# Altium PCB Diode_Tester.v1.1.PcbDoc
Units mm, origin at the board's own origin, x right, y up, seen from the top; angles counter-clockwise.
Board outline 69.07 x 78.33 mm, 2 copper layers (Top Layer, Bottom Layer); 64 components, 44 nets, 206 pads, 103 vias.
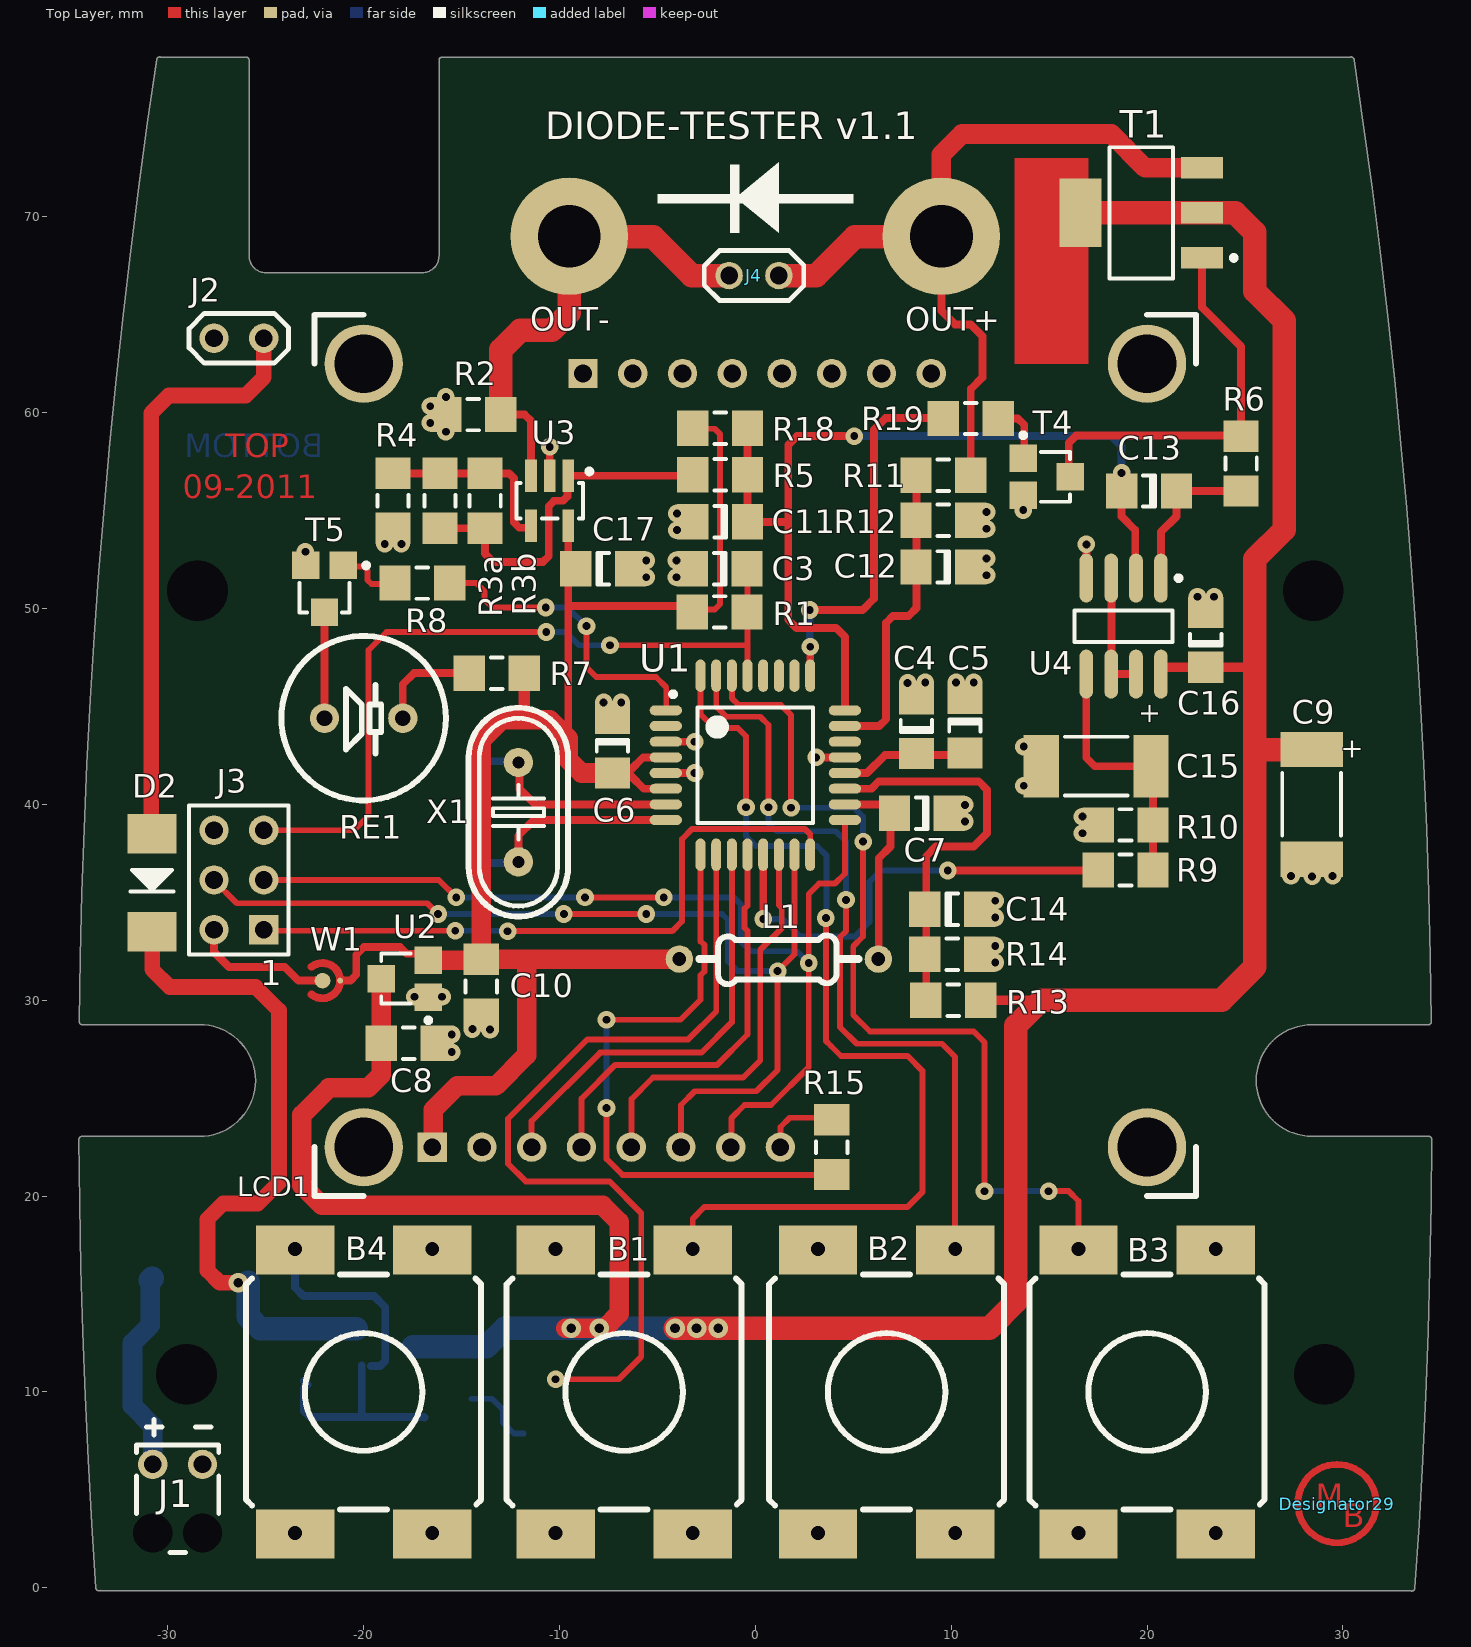
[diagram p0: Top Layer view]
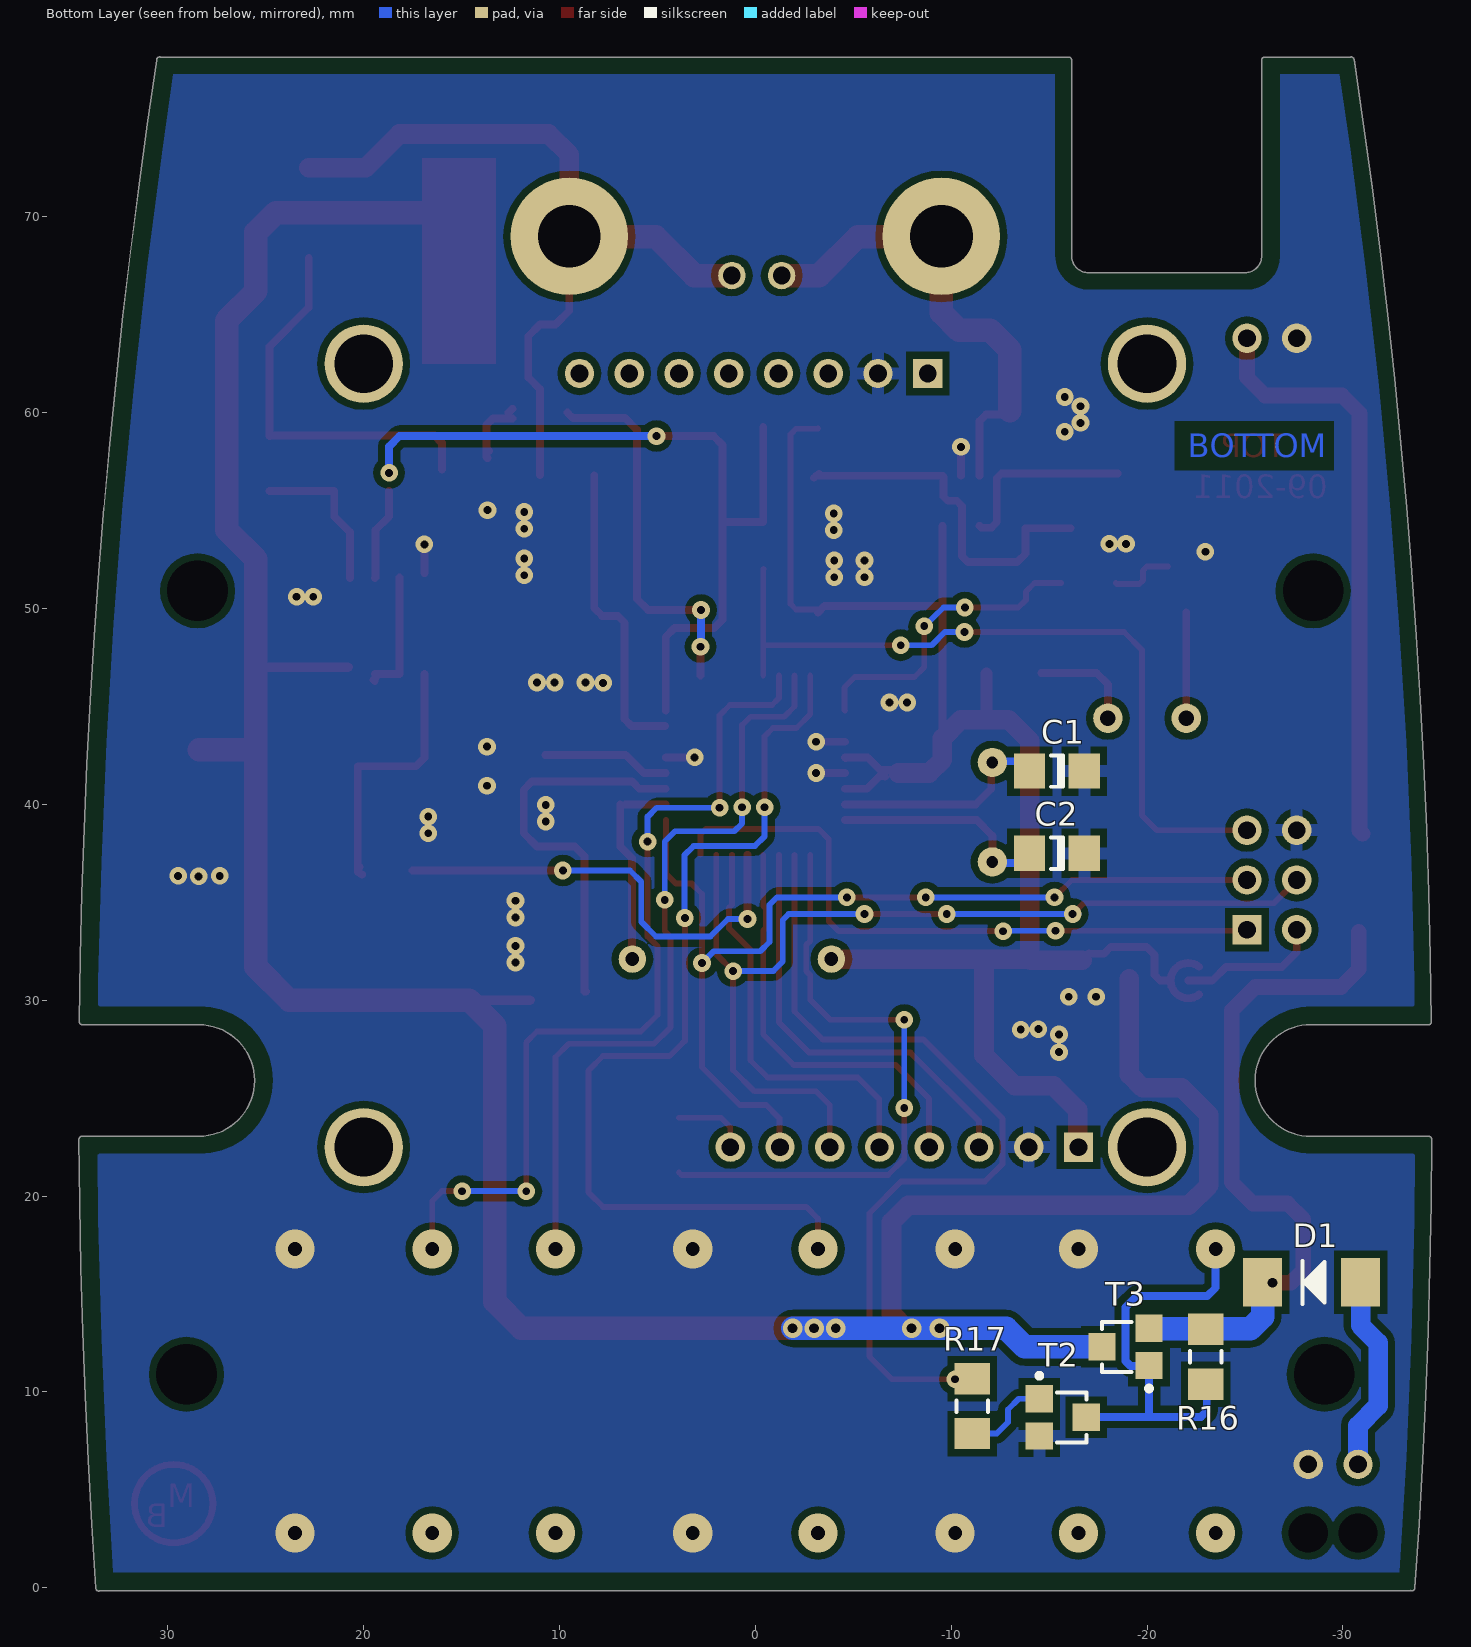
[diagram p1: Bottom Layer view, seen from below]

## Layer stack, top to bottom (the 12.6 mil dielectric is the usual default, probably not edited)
Top Layer: signal copper 0.0356
Dielectric: dielectric 0.32, FR-4, Dk 4.8
Bottom Layer: signal copper 0.0356

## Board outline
-33.673,-0.012 cw(c322.959,24.879) -34.535,22.899 cw(c-34.385,22.9) -34.343,23.044 cw(c-34.3,22.9) -34.3,23.05 -28.37,23.05 ccw(c-28.37,25.9) -25.52,25.9 ccw(c-28.37,25.9) -28.37,28.75 -34.3,28.75 cw(c-34.3,28.9) -34.336,28.754 cw(c-34.368,28.901) -34.518,28.902 cw(c322.959,24.879) -30.567,78.033 cw(c-30.419,78.01) -30.363,78.15 cw(c-30.35,78) -30.35,78.15 -26,78.15 cw(c-26,78) -25.85,78 -25.85,68 cw(c-26,68) -25.85,67.999 cw(c-25,68) -25.85,68 -25.85,67.999 ccw(c-25,68) -25,67.15 -17,67.15 ccw(c-17,68) -16.15,67.999 ccw(c-17,68) -16.15,68 -16.15,78 cw(c-16,78) -16,78.15 30.364,78.15 cw(c30.419,78.01) 30.55,78.084 cw(c30.425,78) 30.575,78 cw(c30.425,78) 30.575,77.985 cw(c-322.959,24.879) 34.518,28.904 cw(c34.368,28.902) 34.518,28.902 cw(c34.368,28.902) 34.338,28.755 cw(c34.3,28.9) 34.3,28.75 28.42,28.75 ccw(c28.42,25.9) 28.42,23.05 34.35,23.05 cw(c34.35,22.9) 34.368,23.049 cw(c34.385,22.9) 34.535,22.9 cw(c34.385,22.9) 34.535,22.899 cw(c-322.959,24.879) 33.672,-0.026 cw(c33.522,-0.016) 33.444,-0.144 cw(c33.4,0) 33.4,-0.15 -33.4,-0.15 cw(c-33.4,0) -33.46,-0.138 cw(c-33.523,-0.002)

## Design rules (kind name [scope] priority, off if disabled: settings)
Clearance Clearance_1 [InNet('GND') And OnLayer('Bottom Layer')] p1: gap=0.35
Clearance [All] p2: gap=0.25
ComponentClearance [All] p1: gap=0.254 collisioncheckmode=3 verticalgap=0.254
ComponentClearance ComponentClearance_1 [All] p2: gap=0.254 collisioncheckmode=0 verticalgap=0.254
DiffPairsRouting DiffPairsRouting_1 [All] p2: maxlimit=0.254 minlimit=0.254 mostfreqgap=0.254 maxuncoupledlength=12.7
FanoutControl Fanout_LCC [IsLCC] p1: bgadir=Out bgaviamode=Centered fanoutstyle=Auto fanoutdirection=Alternating viagrid=0.025 // Fanout_LCC (Default Rule)
FanoutControl Fanout_BGA [IsBGA] p2: bgadir=Out bgaviamode=Centered fanoutstyle=Auto fanoutdirection=Alternating viagrid=0.025 // Fanout_BGA (Default Rule)
FanoutControl Fanout_Default [All] p4: bgadir=Out bgaviamode=Centered fanoutstyle=Auto fanoutdirection=Alternating viagrid=0.025 // Fanout_Default (Default Rule)
FanoutControl Fanout_Small [(CompPinCount < 5)] p5: bgadir=Out bgaviamode=Centered fanoutstyle=Auto fanoutdirection=OutThenIn viagrid=0.025 // Fanout_Small (Default Rule)
FanoutControl Fanout_BGA_1 [IsBGA] p6: bgadir=Out bgaviamode=Centered fanoutstyle=Auto fanoutdirection=Alternating viagrid=0.025 // Fanout_BGA (Default Rule)
FanoutControl Fanout_LCC_1 [IsLCC] p7: bgadir=Out bgaviamode=Centered fanoutstyle=Auto fanoutdirection=Alternating viagrid=0.025 // Fanout_LCC (Default Rule)
FanoutControl Fanout_SOIC_1 [IsSOIC] p8: bgadir=Out bgaviamode=Centered fanoutstyle=Auto fanoutdirection=Alternating viagrid=0.025 // Fanout_SOIC (Default Rule)
FanoutControl Fanout_Small_1 [(CompPinCount < 5)] p9: bgadir=Out bgaviamode=Centered fanoutstyle=Auto fanoutdirection=OutThenIn viagrid=0.025 // Fanout_Small (Default Rule)
FanoutControl Fanout_Default_1 [All] p10: bgadir=Out bgaviamode=Centered fanoutstyle=Auto fanoutdirection=Alternating viagrid=0.025 // Fanout_Default (Default Rule)
Height Height_1 [All] p2: minheight=0 maxheight=25.4 prefheight=12.7
HoleSize [All] p1: absolutevalues=TRUE maxlimit=5 minlimit=0.3 maxpercent=80.000 minpercent=20.000
LayerPairs LayerPairs_1 [All] p2: enforce=TRUE
PasteMaskExpansion PasteMaskExpansion_1 [All] p2: expansion=0
PlaneClearance PlaneClearance_1 [All] p2: clearance=0.508
PolygonConnect PolygonConnect_1 [(InComponent('J1') OR InComponent('J2'))] p1: connectstyle=Direct reliefconductorwidth=0.254 reliefentries=4 polygonreliefangle="90 Angle"
PolygonConnect PolygonConnect_GND1 [IsVia] p2: connectstyle=Direct reliefconductorwidth=0.254 reliefentries=4 polygonreliefangle="90 Angle"
PolygonConnect [All] p3: connectstyle=Relief reliefconductorwidth=0.635 reliefentries=4 polygonreliefangle="90 Angle"
RoutingPriority RoutingPriority_1 [All] p2: routingpriority=0
RoutingTopology RoutingTopology_1 [All] p2: topology=Shortest
RoutingVias [All] p1: holewidth=0.6 width=2 viastyle="Through Hole" minholewidth=0.3 minwidth=1.2 maxholewidth=3 maxwidth=5
ShortCircuit ShortCircuit_2 [All] p1: allowed=FALSE
ShortCircuit [All] p2: allowed=FALSE
ShortCircuit ShortCircuit_1 [All] p3: allowed=FALSE
SolderMaskExpansion [All] p1: expansion=0.102
SolderMaskExpansion SolderMaskExpansion_1 [All] p2: expansion=0.102
TestPointUsage [All] p1: valid=0 allowmultiple=FALSE
TestPointUsage TestPointUsage_1 [All] p2: valid=0 allowmultiple=FALSE
Testpoint [All] p1: side=15 testpointundercomponent=TRUE minsize=1.016 maxsize=2.54 preferedsize=1.524 minholesize=0 maxholesize=1.016 preferedholesize=0.813 testpointgrid=0.025 style=1023 order=0-112345678
Testpoint Testpoint_1 [All] p2: side=15 testpointundercomponent=TRUE minsize=1.016 maxsize=2.54 preferedsize=1.524 minholesize=0 maxholesize=1.016 preferedholesize=0.813 testpointgrid=0.025 style=1023 order=0123456789
UnRoutedNet UnRoutedNet_1 [All] p2:
Width [All] p1: maxlimit=5 minlimit=0.3 preferedwidth=0.305 toplayer_prefwidth=0.8 bottomlayer_prefwidth=0.8 minimp=50.000000 maximp=50.000000 favimp=50.000000
12 further rules are at their usual default settings.

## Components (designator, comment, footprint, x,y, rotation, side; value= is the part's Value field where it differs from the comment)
B1 "3xSMS-G1612" TACTM-24N-F2 -6.7,10 r0 top
B2 "SMS-G1612" TACTM-24N-F2 6.7,10 r0 top
B3 "SMS-G1612" TACTM-24N-F2 20,10 r0 top
B4 "SMS-G1612" TACTM-24N-F2 -20,10 r0 top
C1 "Cap" C1206 -15.4,41.7 r0 bottom
C2 "Cap" C1206 -15.4,37.5 r0 bottom
C3 "Cap" C1206 -1.825,52.025 r180 top
C4 "Cap" C1206 8.225,44 r90 top
C5 "Cap" C1206 10.7,44.025 r270 top
C6 "Cap" C1206 -7.3,43 r270 top
C7 "Cap" C1206 8.5,39.55 r180 top
C8 "Cap" 3216[1206] -17.7,27.8 r0 top
C9 "Cap Pol2" 6332[2512]_POL 28.4,40 r270 top
C10 "Cap" 3216[1206] -14,30.7 r270 top
C11 "Cap" C1206 -1.8,54.425 r180 top
C12 "Cap" C1206 9.6,52.125 r180 top
C13 "Cap" C1206 20.1,56 r180 top
C14 "Cap" C1206 10.05,34.65 r0 top
C15 "Cap Pol2" 6332[2512]_POL 17.4,41.95 r180 top
C16 "Cap" C1206 23,48.4 r90 top
C17 "Cap" C1206 -7.775,52.025 r0 top
D1 "1N5819" MELF2 -28.4,15.6 r0 bottom
D2 "1N5819" MELF2 -30.8,36 r270 top
Designator29 "Comment" LOGO_TOP 29.7,4.3 r0 top
J1 "9V Batt." "Battery Cable" -29.5,6.3 r0 top
J2 "Ext" J_HDR2X1#1 -25.1,63.8 r90 top
J3 "S2G20 3x" HDR2X3 -25.1,33.6 r90 top
J4 "Ext" J_HDR2X1#2 1.2,67 r90 top
L1 "10uH" AXIAL 1.2,32.1 r180 top
LCD1 "Nokia 3110/5110" N5110LCD -22.5,20 r0 top locked
OUT+ "Test Point" "HOLE 6.0/3.2"#1 5,68.9 r0 top
OUT- "Test Point" "HOLE 6.0/3.2"#2 -6.4,68.9 r0 top
R1 "Res2" 3216[1206] -1.825,49.825 r180 top
R2 "Res2" 3216[1206] -14.4,59.9 r180 top
R3a "Res2" 3216[1206] -16.1,55.5 r90 top
R3b "Res2" 3216[1206] -13.8,55.5 r90 top
R4 "Res2" 3216[1206] -18.5,55.5 r270 top
R5 "Res2" 3216[1206] -1.8,56.825 r180 top
R6 "Res2" 3216[1206] 24.8,57.4 r90 top
R7 "Res2" 3216[1206] -13.2,46.7 r180 top
R8 "Res2" 3216[1206] -17,51.3 r0 top
R9 "Res2" 3216[1206] 18.9,36.65 r0 top
R10 "Res2" 3216[1206] 18.9,38.95 r0 top
R11 "Res2" 3216[1206] 9.6,56.8 r180 top
R12 "Res2" 3216[1206] 9.6,54.5 r0 top
R13 "Res2" 3216[1206] 10.1,30 r180 top
R14 "Res2" 3216[1206] 10.05,32.35 r180 top
R15 "Res2" 3216[1206] 3.9,22.5 r90 top
R16 "Res2" 3216[1206] -23,11.8 r90 bottom
R17 "Res2" 3216[1206] -11.075,9.275 r270 bottom
R18 "Res2" 3216[1206] -1.8,59.2 r0 top
R19 "Res2" 3216[1206] 11,59.7 r0 top
RE1 "Piezzo" "KPB1220 Small" -20,44.4 r180 top
T1 "BCP56" SOT223 19.7,70.2 r90 top
T2 "BC817" SOT23-3 -15.7,8.7 r270 bottom
T3 "IRLML9301TRPbF" SOT23-3 -18.9,12.3 r90 bottom
T4 "BC817" SOT23-3 14.875,56.725 r270 top
T5 "BC817" SOT23-3 -22,51 r180 top
U1 "ATmega168-20AU" TQFP32_N 0,42 r0 top
U2 "MCP1702-3.3V" SOT23-3 -17.9,31.1 r90 top
U3 "MCP6071" SOT23-5 -10.5,55.5 r180 top
U4 "TS912" SO8_M 18.8,49.1 r270 top
W1 "Solder Bridge" "Solder Bridge" -22.1,31 r0 top
X1 "16MHz" HC49 -12.1,39.6 r90 top

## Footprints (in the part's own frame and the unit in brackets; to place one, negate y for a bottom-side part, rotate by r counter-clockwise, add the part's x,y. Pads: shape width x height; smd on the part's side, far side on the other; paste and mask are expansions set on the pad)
3216[1206] [mm] "Chip Resistor; Body 3.2 x 1.6 mm (LxW typ)"
  rect 1.6x1.8 smd: 1(-1.4,0) 2(1.4,0)
  silkscreen extent -0.3,-0.8 0.3,0.8
6332[2512]_POL [mm]
  rect 1.8x3.2 smd: 1(-2.8,0) 2(2.8,0)
  silkscreen extent -1.6,-1.5 1.6,1.5
AXIAL [mm] "Resistor; 2 Leads"
  round 1.4 hole 0.7: 1(-5.08,0) 2(5.08,0)
  silkscreen extent -4.06,-1.21 4.06,1.28
"Battery Cable" [mm]
  round 1 hole 2: 0(-1.27,-3.5) 0(1.27,-3.5)
  round 1.5 hole 0.9: 1(-1.27,0) 2(1.27,0)
  silkscreen extent -2.1,-4.5 2.1,2.3
C1206 [mm] "Chip Capacitor; Body 3.2 x 1.6 mm (LxW typ)"
  rect 1.6x1.8 smd: 1(-1.4,0) 2(1.4,0)
  silkscreen extent -0.3,-0.8 0.3,0.8
HC49 [mm]
  round 1.5 hole 0.6: 1(-2.54,0) 2(2.54,0)
  silkscreen extent -5.33,-2.54 5.33,2.54
HDR2X3 [mm] "Connector; Header; 3x2 Position"
  rect 1.5x1.5 hole 0.9: 1(0,0)
  round 1.5 hole 0.9: 2(0,2.54) 3(2.54,0) 4(2.54,2.54) 5(5.08,0) 6(5.08,2.54)
  silkscreen extent -1.27,-1.27 6.35,3.81
"HOLE 6.0/3.2"#1 [mm]
  round 6 hole 3.2: 1(4.5,0.1)
"HOLE 6.0/3.2"#2 [mm]
  round 6 hole 3.2: 1(-3.1,0.1)
J_HDR2X1#1 [mm] "Connector; Header; 3x2 Position"
  round 1.5 hole 0.9: 1(0,0) 2(0,2.54)
  silkscreen extent -1.27,-1.27 1.27,3.81
J_HDR2X1#2 [mm] "Connector; Header; 3x2 Position"
  round 1.4 hole 0.9: 1(0,0) 2(0,2.54)
  silkscreen extent -1.27,-1.27 1.27,3.81
"KPB1220 Small" [mm]
  round 1.5 hole 0.8: 1(-2,0) 2(2,0)
  silkscreen extent -4.2,-4.2 4.2,4.2
LOGO_TOP [mm]
  Top Layer lines w0.35: -2,0 cw(c0,0) 2,0 cw(c0,0) -2,0
MELF2 [mm]
  rect 2x2.5 smd: 1(-2.5,0) 2(2.5,0)
  silkscreen extent -0.65,-1.1 0.46,1.1
N5110LCD [mm]
  round 4 hole 3: 0(2.5,2.5) 0(2.5,42.5) 0(42.5,2.5) 0(42.5,42.5)
  rect 1.5x1.5 hole 0.9: 1(6,2.5) 1(13.7,42)
  round 1.5 hole 0.9: 2(8.54,2.5) 2(16.24,42) 3(11.08,2.5) 3(18.78,42) 4(13.62,2.5) 4(21.32,42) 5(16.16,2.5) 5(23.86,42) 6(18.7,2.5) 6(26.4,42) 7(21.24,2.5) 7(28.94,42) 8(23.78,2.5) 8(31.48,42)
  silkscreen extent 0,0 45,45
SO8_M [mm] "SOIC, 8-Leads, Body 4.9x3.9mm, Pitch 1.27mm, IPC Low Density"
  oval 2.5x0.7 smd: 1(-2.45,1.905) 2(-2.45,0.635) 3(-2.45,-0.635) 4(-2.45,-1.905) 5(2.45,-1.905) 6(2.45,-0.635) 7(2.45,0.635) 8(2.45,1.905)
  silkscreen extent -2.57,-2.5 0.8,2.93, body extent -2,-2.5 2,2.5, height 1.75
"Solder Bridge" [mm]
  round 0.8 smd: 1(0,0)
  round 0.3 smd mask+0: 2(0.9,0)
  Top Layer lines w0.4: -0.554,-0.709 ccw(c0,0) 0.9,0 ccw(c0,0) -0.554,0.709
SOT23-3 [mm] "SOT-23; 3 Leads; Body 3.0 x 2.5 mm, inc. leads (LxW max)"
  rect 1.4x1.4 smd: 1(-0.95,-1.2) 2(0.95,-1.2) 3(0,1.2)
  silkscreen extent -2.25,-1.33 1.27,1.2
SOT23-5 [mm] "SOT-23/SC-74A; 5 Leads; Body 3.1 x 3 mm, inc. leads (LxW max)"
  rect 0.6x1.65 smd: 1(-0.95,-1.275) 2(0,-1.275) 3(0.95,-1.275) 4(0.95,1.275) 5(-0.95,1.275)
  silkscreen extent -2.15,-1.62 1.7,0.9
SOT223 [mm] "SOT-223/SC-73; 4 Leads; Body 6.7 x 7.3 mm, inc. leads (LxW max)"
  rect 1.1x2.15 smd: 1(-2.3,-3.1) 2(0,-3.1) 3(2.3,-3.1)
  rect 3.5x2.15 smd: 4(0,3.1)
  silkscreen extent -3.35,-4.85 3.35,1.63
TACTM-24N-F2 [mm]
  rect 4x2.5 smd: 1(-3.5,7.25) 2(-3.5,-7.25) 3(3.5,7.25) 4(3.5,-7.25)
  silkscreen extent -6,-6 6,6
TQFP32_N [mil] "32-Pin Thin Quad Flat Pack 0.8 mm Pitch, IPC Medium Density"
  oval 65x20 smd: 1(-180,110.24) 2(-180,78.74) 3(-180,47.24) 4(-180,15.75) 5(-180,-15.75) 6(-180,-47.24) 7(-180,-78.74) 8(-180,-110.24) 17(180,-110.24) 18(180,-78.74) 19(180,-47.24) 20(180,-15.75) 21(180,15.75) 22(180,47.24) 23(180,78.74) 24(180,110.24)
  oval 20x65 smd: 9(-110.24,-180) 10(-78.74,-180) 11(-47.24,-180) 12(-15.75,-180) 13(15.75,-180) 14(47.24,-180) 15(78.74,-180) 16(110.24,-180) 25(110.24,180) 26(78.74,180) 27(47.24,180) 28(15.75,180) 29(-15.75,180) 30(-47.24,180) 31(-78.74,180) 32(-110.24,180)
  silkscreen extent -170,-116 116,148

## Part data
B1 B2 B3 B4: library part Button
C1 C2 C3 C4 C5 C6 C7 C10 C11 C12 C13 C14 C16 C17: "Capacitor"
C8: library part "Cap Pol2", "Polarized Capacitor (Axial)"
C9 C15: "Polarized Capacitor (Axial)"
D1 D2: library part "Diode 11DQ03", "Schottky Rectifier"
J1 J2 J4: library part "Header 2", "Header, 2-Pin"
J3: library part "Header 3X2", "Header, 3-Pin, Dual row"
L1: library part Inductor
LCD1: library part N5110LCD, "N5110LCD"
R1 R2 R3a R3b R4 R5 R6 R7 R8 R9 R10 R11 R12 R13 R14 R15 R16 R17 R18 R19: "Resistor"
RE1: library part Speaker, "Loudspeaker"
T1: library part PNP, "PNP Bipolar Transistor"
T2: library part NPN, "NPN Bipolar Transistor"
T3: library part MOSFET-P, "P-Channel MOSFET"
T4 T5: library part BC846B, "NPN General-purpose Transistor"
U1: library part ATmega48/88/168_TQFP_B, "ATmega48/88/168"
U2: library part LF50ABDT, "500mA, Very Low Drop (0.45V) Voltage Regulator"
U3: library part "OpAmp Single 2", "OpAmp"
U4: library part "OpAmp Dual 2", "OpAmp"
X1: library part XTAL, "Crystal Oscillator"

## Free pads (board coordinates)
  round 2 hole 3.1 mask+0.075: 0(-29.05,10.9) 0(-28.48,50.9) 0(29.05,10.9) 1(28.48,50.9)

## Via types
v1: diameter 0.9, hole 0.4, Top Layer to Bottom Layer, tented both sides, 81 vias
v2: diameter 2, hole 0.7, Top Layer to Bottom Layer, 16 vias
v3: diameter 1, hole 0.5, Top Layer to Bottom Layer, tented both sides, 6 vias

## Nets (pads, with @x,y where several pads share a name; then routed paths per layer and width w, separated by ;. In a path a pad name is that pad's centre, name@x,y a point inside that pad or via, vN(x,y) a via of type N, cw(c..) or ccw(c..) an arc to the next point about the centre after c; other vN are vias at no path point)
+3.3V: C6.2 C10.1 C17.1 L1.2 LCD1.1@-16.5,22.5 R1.2 R7.1 R18.1 U1.4 U1.6 U2.2 U3.5 W1.2 | length 87.8
  Top Layer w0.3: R1.2@-3.35,49.95 -2.075,49.95 -1.8,50.225 -1.8,58.9 -2.075,59.175 -3.175,59.175 R18.1
  Top Layer w0.4: W1.2 -20.675,31 -20.375,31.3 -20.375,32.325 -19.975,32.725 -18.15,32.725 -17.8,32.375 -17.05,32.375 U2.2@-17.025,32.4 ; U2.2 U2.2@-16.65,32.1 ; -9.55,43.375 U3.5 ; -9.55,50.125 -3.525,50.125 R1.2@-3.2,49.8 ; C6.2@-6.85,41.75 -6.375,41.75 -5.725,42.4 U1.4 U1.4@-4.597,42.375 ; C6.2@-6.613,41.413 -6.575,41.45 -6.35,41.45 -5.7,40.8 U1.6
  Top Layer w0.6: R7.1 -11.8,44.35 -11.775,44.325
  Top Layer w1: U2.2 -14.05,32.05 C10.1 ; LCD1.1@-16.45,22.55 -16.45,24.4 -15.225,25.625 -13.25,25.625 -11.675,27.2 -11.675,32.1 ; C6.2 -8.875,41.6 -9.55,42.275 -9.55,43.375 -10.5,44.325 -12.925,44.325 -14,43.25 C10.1 ; L1.2 C10.1
AREF: C4.1 C5.2 U1.20 | length 6.5
  Top Layer w0.4: U1.20 5.7,41.6 6.625,42.525 C5.2@10.725,42.525
GND: B1.1 B1.2 B2.1 B2.2 B3.3 B3.4 B4.3 C1.1 C2.1 C3.2 C4.2 C5.1 C6.1 C7.1 C8.2 C9.2 C10.2 C11.2 C12.1 C14.2 C15.2 C16.2 C17.2 J1.2 J2.2 J3.6 LCD1.2 R2.2 R4.2 R10.1 R12.2 R14.1 T2.2 T4.2 T5.2 U1.3 U1.5 U1.21 U2.1 U3.2 U4.4 | length 7.4
  Top Layer w0.4: U3.2 v1(-10.5,58.25) ; U1.5 v1(-3.1,41.6) ; U1.3 v1(-3.1,43.2) ; v1(3.1,42.4) U1.21 ; U4.4@16.9,51.8 v1(16.9,53.272)
  other v1: -15.5,27.35 -15.5,28.25 -13.55,28.5 -14.45,28.525 -17.4,30.175 -16,30.175 12.25,31.925 12.25,32.775 12.25,34.225 12.25,35.075 28.425,36.325 27.35,36.35 29.475,36.35 16.7,38.525 10.7,39.125 16.7,39.375 10.7,39.975 13.7,40.95 13.7,42.95 -7.75,45.2 -6.85,45.2 7.775,46.2 8.675,46.225 10.25,46.225 11.15,46.225 22.575,50.6 23.425,50.6 -5.575,51.6 -4.025,51.6 11.8,51.7 -5.575,52.45 -4.025,52.45 11.8,52.55 -22.975,52.9 -18.925,53.3 -18.075,53.3 -4,54 11.8,54.075 -4,54.85 11.8,54.925 13.675,55.025 -15.8,59.025 -16.6,59.475 -16.6,60.325 -15.8,60.8
  other v2: -10.2,2.8 3.2,2.8 23.5,2.8 -16.5,17.3 -10.2,17.3 3.2,17.3 23.5,17.3
I_MEAS: C11.1 C13.2 R5.1 R18.2 U1.24 U4.2 | length 46.4
  Top Layer w0.4: R18.2@-0.4,59.275 C11.1 1.675,54.425 ; U1.24 4.575,44.803 4.575,48.55 4.125,49 2.1,49 1.675,49.425 1.675,58.35 2.125,58.8 v1(5.05,58.8) ; C13.2 18.7,54.7 19.4,54 19.4,51.585 U4.2
  Bottom Layer w0.4: v1(5.05,58.8) 18.175,58.8 18.7,58.275 v1(18.7,56.925)
I_SET: R9.1 U1.13 | length 23.3
  Top Layer w0.4: v1(0.4,34.15) U1.13 ; v1(9.825,36.625) R9.1@17.5,36.625
  Bottom Layer w0.3: v1(0.4,34.15) 1.4,34.15 2.3,33.25 5.075,33.25 5.825,34 5.825,36.05 6.4,36.625 v1(9.825,36.625)
MISO: J3.1 U1.16 | length 33.9
  Top Layer w0.3: J3.1 -25.05,33.55 v1(-15.325,33.55) ; v1(-12.65,33.525) -4.25,33.525 -3.75,34.025 -3.75,38.225 -3.225,38.75 2.525,38.75 2.8,38.475 U1.16
  Bottom Layer w0.3: v1(-15.325,33.55) v1(-12.65,33.525)
  Bottom Layer w0.4: v1(-12.65,33.525) v1@-12.475,33.4
MOSI: J3.4 LCD1.6@-3.8,22.5 U1.15 | length 51.4
  Top Layer w0.3: J3.4 -27.64,36.115 -26.475,34.95 -16.75,34.95 v1(-16.2,34.4) ; v1(-9.775,34.4) v1(-5.575,34.4) ; LCD1.6@-3.8,22.5 -3.8,24.65 -3.1,25.35 0.05,25.35 1.138,26.438 v1(1.138,31.488) 2,32.35 U1.15
  Bottom Layer w0.3: v1@-16.5,34.4 v1(-9.775,34.4) ; v1(-5.575,34.4) -1.7,34.4 -1.4,34.1 -1.4,31.975 -0.925,31.5 1.125,31.5 v1(1.138,31.488)
NetB4_1: B4.1 R16.1 T2.3 T3.1 | length 21.3
  Bottom Layer w0.3: T2.3@-16.975,8.775 T2.3
  Bottom Layer w0.4: v2(-23.5,17.3) -23.5,15.325 -23.075,14.9 -19.475,14.9 -18.9,14.325 -18.9,11.575 -19.15,11.325 T3.1@-19.625,11.325 ; R16.1@-23.05,10.55 -22.875,10.375 -23.05,10.2 -23.05,9.025 -22.75,8.725 -16.925,8.725 T2.3 ; T3.1 -20.1,8.75 -20.075,8.725
NetC7_2: C7.2 L1.1 U1.18 | length 10.2
  Top Layer w0.4: U1.18 C7.2@6.625,40 ; L1.1 6.3,32.121 6.3,37.25 6.9,37.85 C7.2@6.9,40
NetC13_1: C13.1 R6.1 U4.1 | length 8.1
  Top Layer w0.4: U4.1 20.705,53.905 21.5,54.7 C13.1 R6.1
NetC15_1: C15.1 R9.2 R10.2 U4.5 | length 13.7
  Top Layer w0.4: U4.5 16.895,42.38 17.325,41.95 C15.1 20.3,41.95 20.3,36.55 R9.2@20.075,36.425 ; R9.2@20.2,36.8 R9.2@20.3,36.7
NetD1_1: D1.1 J1.1 | length 10.3
  Bottom Layer w1: D1.1@-30.9,15.7 -30.9,13.4 -31.8,12.5 -31.8,9.3 -30.77,8.27 J1.1
  Bottom Layer w1.2: D1.1@-30.9,15.7 D1.1@-30.8,15.8
NetD1_2: D1.2 D2.2 R16.2 T3.2 | length 34.5
  Top Layer w0.8: D2.2 -30.8,31.575 -29.9,30.675 -25.525,30.675 -24.325,29.475 -24.325,20.7 -25.4,19.625 -27.175,19.625 -27.975,18.825 -27.975,16.2 -27.35,15.575 v3(-26.4,15.575)
  Bottom Layer w1.2: D1.2 -25.9,13.85 -25.275,13.225 T3.2@-20.375,13.225
NetD2_1: D2.1 J2.1 | length 30
  Top Layer w0.8: D2.1@-31,38.5 -30.85,38.65 -30.85,59.975 -29.95,60.875 -26.025,60.875 -25.1,61.8 J2.1
NetJ3_2: J3.2 W1.1 | length 7.3
  Top Layer w0.4: J3.2 -27.64,32.465 -26.875,31.7 -24.025,31.7 -23.325,31 W1.1
NetJ4_1: J4.1 OUT+.1 R11.1 T1.3 | length 38.9
  Top Layer w0.4: OUT+.1@9.5,68.7 9.5,65.2 10.2,64.5 11,64.5 11.6,63.9 11.6,61.8 11,61.2 R11.1
  Top Layer w1: OUT+.1 9.5,73.175 10.55,74.225 18.175,74.225 19.9,72.5 T1.3
  Top Layer w1.2: J4.1 3.11,67 5.085,68.975 OUT+.1@7.16,68.975
NetJ4_2: J4.2 OUT-.1 R2.1 U3.3 | length 22.5
  Top Layer w0.4: R2.1 -11.775,59.9 -11.45,59.575 U3.3
  Top Layer w1.2: R2.1@-13,60.1 -13,63.2 -12,64.2 -10.4,64.2 -9.5,65.1 OUT-.1 ; OUT-.1@-7.3,68.975 -5.225,68.975 -3.25,67 J4.2
NetLCD1_8: LCD1.8@1.28,22.5 R15.2 | length 3.8
  Top Layer w0.3: LCD1.8@1.28,22.5 1.28,23.53 1.75,24 R15.2@3.9,24
NetR3a_1: R3a.1 R3b.1 R5.2 U3.1 | length 18.6
  Top Layer w0.4: R3a.1 R3b.1 -13.8,52.8 -13.375,52.375 -10.85,52.375 -10.55,52.675 -10.55,55.225 -10.275,55.5 -9.825,55.5 -9.6,55.725 -9.6,56.725 U3.1 -3.1,56.775 R5.2@-3,56.675 ; R5.2@-3.25,56.875 R5.2
NetR3a_2: R3a.2 R3b.2 R4.1 U3.4 | length 9.6
  Top Layer w0.4: R4.1 -12.575,56.9 -12.325,56.65 -12.325,54.4 -12.05,54.125 -11.55,54.125 U3.4
NetR6_2: R6.2 T1.1 T4.3 | length 20.2
  Top Layer w0.4: T4.3@16,57.1 16,58.45 16.375,58.825 24.775,58.825 R6.2 24.8,63.375 22.8,65.375 T1.1
NetR7_2: R7.2 RE1.1 | length 5.4
  Top Layer w0.4: RE1.1 -18,46.125 -17.425,46.7 R7.2
NetR8_1: R8.1 T5.1 | length 3.4
  Top Layer w0.3: T5.1@-21.075,52.15 -20,52.15 -19.8,51.95 -19.8,51.45 -19.6,51.25 -18.45,51.25 R8.1
NetR17_2: R17.2 T2.1 | length 3.8
  Bottom Layer w0.3: T2.1 -13.45,9.65 -12.9,9.1 -12.9,8.45 -12.325,7.875 R17.2@-11.825,7.875
NetR19_2: R19.2 T4.1 | length 3.6
  Top Layer w0.4: R19.2 13.4,59.7 13.725,59.375 13.725,57.725 T4.1 ; R19.2@12.4,60.2 R19.2@12.6,60 ; T4.1@13.6,58.05 T4.1@13.7,58.15
NetRE1_2: RE1.2 T5.3 | length 5.4
  Top Layer w0.4: RE1.2 T5.3
NetU4_3: U4.3 U4.6 U4.7 | length 6.4
  Top Layer w0.4: U4.3@18.175,51.585 18.175,46.685 U4.6 U4.7 ; U4.7@19.4,46.465 19.5,46.365 U4.7@19.435,46.3
PB0: LCD1.4@-8.88,22.5 U1.12 | length 21.6
  Top Layer w0.3: LCD1.4@-8.88,22.5 -8.875,22.505 -8.875,24.975 -7.15,26.7 -1.95,26.7 -0.4,28.25 -0.4,33.55 -0.55,33.7 -0.55,34.675 -0.4,34.825 U1.12
PB2: LCD1.5@-6.34,22.5 U1.14 | length 20.9
  Top Layer w0.3: LCD1.5@-6.34,22.5 -6.325,22.515 -6.325,24.95 -5.225,26.05 -0.625,26.05 0.247,26.922 0.247,32.572 1.35,33.675 1.35,34.725 1.2,34.875 U1.14
PC2: R19.1 U1.25 | length 19.4
  Top Layer w0.4: v1(2.775,49.925) 5.475,49.925 6.05,50.5 6.05,59.125 6.65,59.725 9.325,59.725 R19.1@9.6,60 ; U1.25 v1(2.8,48.044)
  Bottom Layer w0.4: v1(2.775,49.925) 2.775,48.069 v1(2.8,48.044)
PD0: B3.1 U1.30 | length 45.5
  Top Layer w0.3: U1.30 -1.2,45.425 -0.85,45.075 1.3,45.075 1.825,44.55 v1(1.825,39.825) ; v1(5.5,38.1) 5.5,33.25 5,32.75 5,29.25 5.85,28.4 11.15,28.4 11.7,27.85 v1(11.7,20.25) ; v1(14.975,20.25) 16,20.25 16.5,19.75 B3.1@16.5,17.55
  Bottom Layer w0.3: v1(1.825,39.825) 5.05,39.825 5.5,39.375 v1(5.5,38.1) ; v1(11.7,20.25) v1(14.975,20.25)
  other v2: 16.5,17.3
PD1: B2.3 U1.31 | length 39.9
  Top Layer w0.3: U1.31 -2,45 -1.475,44.475 0.25,44.475 0.675,44.05 v1(0.675,39.85) ; v1(4.625,35.125) 4.625,33.525 4.325,33.225 4.325,28.625 5.175,27.775 9.525,27.775 10.2,27.1 v2(10.2,17.3)
  Bottom Layer w0.3: v1(0.675,39.85) 0.675,39.025 1.075,38.625 4.1,38.625 4.625,38.1 v1(4.625,35.125)
PD2: B1.3 U1.32 | length 49.4
  Top Layer w0.3: v2(-3.2,17.3) -3.2,18.85 -2.6,19.45 7.775,19.45 8.525,20.2 8.525,26.4 7.775,27.15 4.375,27.15 3.86,27.665 3.6,27.925 v1(3.6,34.2) ; U1.32 -2.8,44.6 -2.1,43.9 -0.9,43.9 -0.475,43.475 v1(-0.475,39.85)
  Bottom Layer w0.3: v1(-0.475,39.85) -0.475,38.375 0.025,37.875 3.15,37.875 3.625,37.4 3.625,34.225 v1(3.6,34.2)
PD3: R8.2 U1.1 | length 15.9
  Top Layer w0.3: R8.2 -14.25,51.3 -13.825,50.875 -13.825,50.45 -13.425,50.05 v1(-10.7,50.05) ; v1(-8.625,49.1) -8.625,47 -8.125,46.5 -5.075,46.5 -4.55,45.975 -4.55,44.822 U1.1
  Bottom Layer w0.3: v1(-10.7,50.05) -9.6,50.05 v1(-8.625,49.1)
PD5: R15.1 U1.9 | length 31.8
  Top Layer w0.3: v1(-7.6,24.5) -7.6,21.9 -6.775,21.075 3.775,21.075 R15.1@3.9,21.2 ; v1(-7.6,29) -3.825,29 -2.8,30.025 -2.8,31.275 -2.6,31.475 -2.6,32.825 -2.775,33 -2.8,33 U1.9
  Bottom Layer w0.3: v1(-7.6,24.5) v1(-7.6,29)
PD6: R17.1 U1.10 | length 43.2
  Top Layer w0.3: v1(-10.2,10.65) -6.975,10.65 -5.825,11.8 -5.825,19.125 -7.45,20.75 -11.725,20.75 -12.625,21.65 -12.625,23.95 -8.575,28 -3.425,28 -2,29.425 U1.10
PD7: LCD1.3@-11.42,22.5 U1.11 | length 22.2
  Top Layer w0.3: LCD1.3@-11.42,22.5 -11.425,22.505 -11.425,23.825 -7.925,27.325 -2.75,27.325 -1.2,28.875 U1.11
RESET: C3.1 J3.5 R1.1 U1.29 | length 39.6
  Top Layer w0.3: J3.5 -20.495,38.68 -19.75,39.425 -19.75,47.875 -18.825,48.8 v1(-10.675,48.8) ; v1(-7.425,48.125) -0.5,48.125 -0.4,48.225 ; C3.1 -0.4,52 U1.29
  Bottom Layer w0.3: v1(-10.675,48.8) -9.675,48.8 -9,48.125 v1(-7.425,48.125)
SCK: J3.3 LCD1.7@-1.26,22.5 U1.17 | length 51.1
  Top Layer w0.3: J3.3 -16.165,36.14 v1(-15.275,35.25) ; v1(-8.7,35.25) v1(-4.675,35.25) ; LCD1.7@-1.26,22.5 -1.225,22.535 -1.225,23.975 -0.55,24.65 0.8,24.65 2.725,26.575 2.725,35.425 3.25,35.95 4.05,35.95 4.572,36.472 U1.17
  Bottom Layer w0.3: v1(-15.275,35.25) v1(-8.7,35.25) ; v1(-4.675,35.25) -1.1,35.25 -0.725,34.875 -0.725,32.975 -0.25,32.5 2.125,32.5 v1(2.725,31.9)
V_BAT: C14.1 R13.2 R14.2 U1.19 | length 20.4
  Top Layer w0.4: U1.19 5.925,40.8 6.3,41.175 11.4,41.175 11.825,40.75 11.825,38.525 11.15,37.85 9.225,37.85 8.725,37.35 R13.2@8.725,30.45 ; R13.2@8.65,30.45 R13.2@8.7,30.5
V_MEAS: C12.2 R11.2 R12.1 U1.23 | length 15.8
  Top Layer w0.3: U1.23 U1.23@4.6,44
  Top Layer w0.4: U1.23@4.6,44 6.325,44 6.675,44.35 6.675,49.275 7.025,49.625 7.825,49.625 8.225,50.025 R11.2@8.225,56.8
VCC: C8.1 C9.1 C16.1 R13.1 T1.2 T1.4 T3.3 U2.3 U4.8 | length 158.3
  Top Layer w0.5: R13.1 14.6,30 ; U4.8@20.8,47 25.5,47
  Top Layer w1: U2.3 -19.1,26.2 -19.775,25.525 -21.775,25.525 -23.15,24.15 -23.15,20.55 -22.125,19.525 -7.8,19.525 -6.95,18.675 -6.95,14 -7.7,13.25 v3@-9.675,13.25
  Top Layer w1.2: v3(-4.1,13.25) 11.95,13.25 13.3,14.6 13.3,28.7 14.6,30 23.8,30 25.5,31.7 25.5,52.525 27,54.025 27,64.7 25.5,66.2 25.5,69.2 24.5,70.2 T1.4 ; 25.5,42.8 C9.1
  Bottom Layer w1.2: T3.3@-17.475,12.3 -13.75,12.3 -12.8,13.25 v3(-1.9,13.25)
  other v3: -9.4,13.25 -7.975,13.25 -3,13.25
XTAL1: C1.2 U1.7 X1.2 | length 11
  Top Layer w0.4: X1.2@-12.04,42.04 -12.04,40.79 -11.25,40 U1.7
  Bottom Layer w0.3: X1.2@-12.16,42.2 X1.2
  Bottom Layer w0.4: C1.2@-14,42.2 X1.2@-12.16,42.2
XTAL2: C2.2 U1.8 X1.1 | length 11.1
  Top Layer w0.4: X1.1@-12.1,37.075 -12.1,38.4 -11.3,39.2 U1.8
  Bottom Layer w0.3: X1.1@-12.16,37 X1.1
  Bottom Layer w0.4: C2.2@-14,37 X1.1@-12.16,37
pads on no net: B1.4 B2.4 B3.2 B4.2 B4.4 J1.0 LCD1.0 LCD1.1@-8.8,62 LCD1.3@-3.72,62 LCD1.4@-1.18,62 LCD1.5@1.36,62 LCD1.6@3.9,62 LCD1.7@6.44,62 LCD1.8@8.98,62 U1.2 U1.22 U1.26 U1.27 U1.28
copper on no net:
  other v2: -23.5,2.8 -16.5,2.8 -3.2,2.8 10.2,2.8 16.5,2.8

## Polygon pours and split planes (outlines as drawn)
GND on Bottom Layer "Bottom Layer-No Net" (solid, remove dead copper, pour order 1000): -36,-1 36,-1 36,78 -36,78 -36,-1

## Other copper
Top Layer:
  region net VCC: 17,73 13.25,73 13.25,62.5 17,62.5
  text "TOP" at -27.075,57.714 h1.2
  text "09-2011" at -29.225,55.639 h1.2
Bottom Layer:
  text "BOTTOM" at -22.075,57.714 h1.2

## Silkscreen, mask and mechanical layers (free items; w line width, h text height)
Top Overlay:
  rectangle: -5,70.675 5,71.175
  region: -0.8,69.175 -0.8,72.675 -1.3,72.675 -1.3,69.175
  region: -1,70.975 1.2,72.775 1.2,69.175
  text "DIODE-TESTER v1.1" at -10.725,73.95 h1.4
Mechanical 1:
  lines w0.3: -34.385,22.9 ccw(c322.959,24.879) -33.523,-0.002 ; -34.368,28.901 cw(c322.959,24.879) -30.419,78.01 ; -34.3,22.9 -28.37,22.9 ccw(c-28.37,25.9) -28.37,28.9 -34.3,28.9 ; -33.4,0 33.4,0 ; -30.35,78 -26,78 -26,68 ccw(c-25,68) -25,67 -17,67 ccw(c-17,68) -16,68 -16,78 30.425,78 ; 30.419,78.01 cw(c-322.959,24.879) 34.368,28.902 ; 33.522,-0.016 ccw(c-322.959,24.879) 34.385,22.9 ; 34.3,28.9 28.42,28.9 ccw(c28.42,25.9) 28.42,22.9 34.35,22.9 ; -34.3,28.9 -34.3,28.9
Mechanical 2:
  region: -25.9,77.3 -25.9,78 -30.25,78 -30.7,76.1 -31.78,68.54 -32.9,57.6 -33.3,52.3 -33.8,46 -34.1,38.2 -34.3,28.9 -28.4,28.9 -27.4,28.8 -26.4,28.2 -25.8,27.4 -25.4,26.6 -25.4,25.4 -25.7,24.5 -26.5,23.6 -27.5,23 -28.3,22.9 -34.4,22.9 -34.3,17.8 -34.1,9.8 -33.5,0.9 -33.4,0 33.4,0 33.8,4.9 34.1,10.1 34.3,17.4 34.3,22.9 28.2,22.9 27.1,23.2 26.2,23.8 25.5,25 25.4,26.2 25.9,27.5 26.8,28.4 27.8,28.9 34.3,28.9 34.2,36.2 33.9,43.5 33.6,49.5 33.1,55.3 32.7,59.9 32.1,65.4 31.4,70.8 30.7,76.3 30.4,78 -15.9,78 -16,67.55 -16.4,67.1 -20.95,67.125 -25.45,67.15 -25.85,67.5
Mechanical 16:
  drawing of 1874 lines, arcs and shapes, not listed
  text "1" at -80.629,132.261 h1
  text "2" at -7.985,132.261 h1
  text "3" at 65.167,132.261 h1
  text "4" at 138.065,132.261 h1
  text "A" at -114.97,109.249 h1
  text "A" at 172.05,109.249 h1
  text "B" at -114.97,61.192 h1
  text "B" at 172.05,61.192 h1
  text "C" at -114.97,12.678 h1
  text "C" at 172.05,12.678 h1
  text "ENGINEER:" at 57.115,-24.33 h1
  text "TITLE:" at 95.215,-24.33 h1
  text "PCB DESIGNER:" at 57.115,-31.823 h1
  text "D" at -114.97,-35.328 h1
  text "D" at 172.05,-35.328 h1
  text "DATE:" at 57.115,-39.57 h1
  text "PART NO.:" at 95.215,-39.57 h1
  text "REV:" at 148.555,-39.57 h1
  text "Altium Limited" at 24.095,-42.11 h1
  text ".PRINT_DATE" at 58.385,-42.618 h1
  text "12a Rodborough Rd" at 24.095,-44.65 h1
  text "Frenchs Forest" at 24.095,-47.19 h1
  text "FILE NAME:" at 57.115,-47.19 h1
  text "DWG NO:" at 95.215,-47.19 h1
  text "SCALE:" at 148.555,-47.19 h1
  text "NSW 2086" at 24.095,-49.73 h1
  text ".PCB_FILE_NAME_NO_PATH" at 58.385,-50.238 h1
  text "1" at -80.629,-55.699 h1
  text "2" at -7.985,-55.699 h1
  text "3" at 65.167,-55.699 h1
  text "4" at 138.065,-55.699 h1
